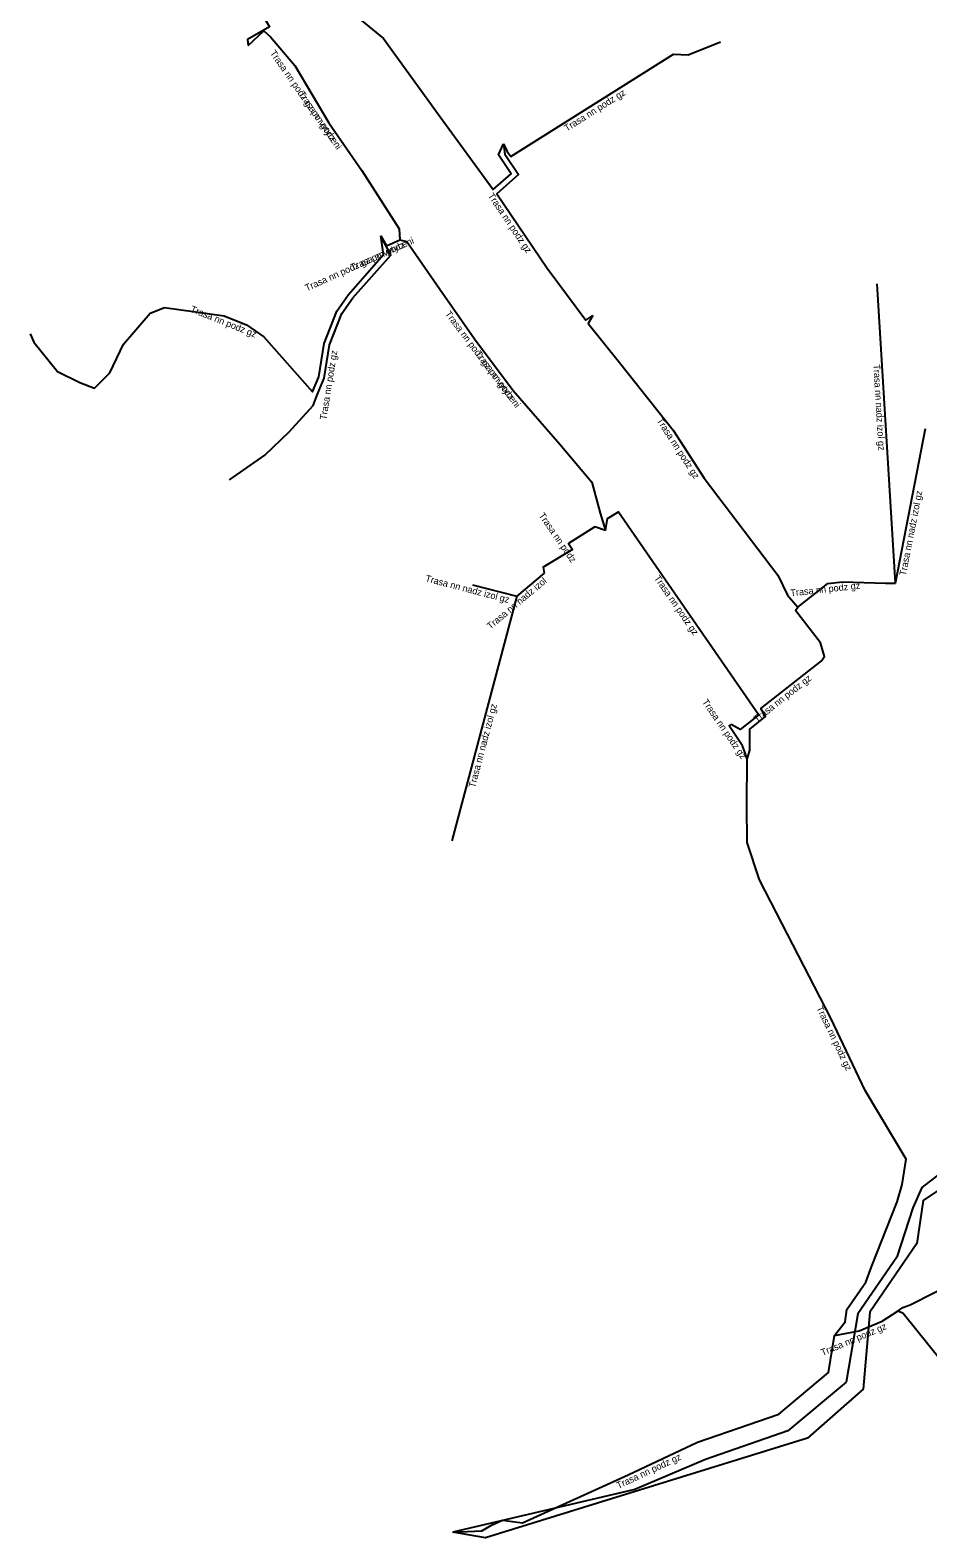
# Model space of a CAD drawing. Extents: x -484846 to -484244, y -1128177 to -1127608.
# Drawn here: x -484614.8 to -484548.8, y -1127966.4 to -1127855.5 of the extents above; entities that cross this region are included whole.
import ezdxf

# ---------------------------------------------------------------- set-up
doc = ezdxf.new("R2010")
doc.units = 0
for name, color, linetype in [('Popiskový text - Ostatní atributy Trasy', 7, 'Continuous'), ('Spojnice NN', 7, 'Continuous'), ('Spojnice VN', 7, 'Continuous')]:
    doc.layers.add(name, color=color, linetype=linetype)

msp = doc.modelspace()

# ---------------------------------------------------------------- linework, layer by layer
at = {"layer": 'Spojnice NN'}
for points in [[(-484612.77, -1127833.18), (-484612.69, -1127833.47), (-484612.45, -1127833.6), (-484612.24, -1127833.6), (-484611.12, -1127832.77), (-484610.26, -1127834.23), (-484608.68, -1127836.16), (-484602.59, -1127846.12), (-484597.23, -1127855.21), (-484598.85, -1127856.15), (-484598.8, -1127856.59)], [(-484599.31, -1127836.35), (-484600.73, -1127837.04), (-484599, -1127840.21), (-484594.48, -1127848.44), (-484591.27, -1127854.08), (-484588.85, -1127856.08), (-484584.69, -1127861.83), (-484580.78, -1127867.2), (-484579.45, -1127866.03), (-484580.4, -1127864.64), (-484580.01, -1127863.82)], [(-484598.8, -1127856.59), (-484597.66, -1127855.5), (-484597.15, -1127855.96), (-484595.37, -1127858.07), (-484592.87, -1127862.29), (-484590.45, -1127865.78), (-484587.69, -1127870.09), (-484587.64, -1127870.9)], [(-484598.8, -1127856.59), (-484597.66, -1127855.5), (-484597.15, -1127855.96), (-484595.37, -1127858.07), (-484592.87, -1127862.29), (-484590.45, -1127865.78), (-484587.69, -1127870.09), (-484587.64, -1127870.9)], [(-484580.01, -1127863.82), (-484579.74, -1127864.38), (-484579.47, -1127864.77), (-484567.52, -1127857.23), (-484566.44, -1127857.28), (-484564.05, -1127856.33)], [(-484580.01, -1127863.82), (-484579.93, -1127864.6), (-484578.93, -1127866.09), (-484580.52, -1127867.5), (-484576.82, -1127872.97), (-484573.97, -1127876.8), (-484573.45, -1127876.47)], [(-484614.84, -1127877.82), (-484614.56, -1127878.43), (-484612.82, -1127880.59), (-484611.19, -1127881.39), (-484610.1, -1127881.81), (-484608.98, -1127880.67), (-484607.97, -1127878.58), (-484606.01, -1127876.28), (-484604.95, -1127875.87), (-484600.57, -1127876.49), (-484598.92, -1127877.15), (-484597.66, -1127878.04), (-484594.07, -1127882.09), (-484593.6, -1127880.97), (-484593.21, -1127878.52), (-484592.27, -1127876.14), (-484591.43, -1127874.91), (-484588.84, -1127871.97), (-484589.05, -1127870.59)], [(-484600.19, -1127888.55), (-484597.57, -1127886.74), (-484595.8, -1127885.01), (-484594.02, -1127883.08), (-484593.7, -1127882.25), (-484593.22, -1127881.07), (-484592.83, -1127878.62), (-484591.91, -1127876.32), (-484591.11, -1127875.15), (-484588.32, -1127872.01), (-484589.05, -1127870.59)], [(-484589.05, -1127870.59), (-484588.62, -1127871.34), (-484587.64, -1127870.9)], [(-484589.05, -1127870.59), (-484588.62, -1127871.34), (-484587.64, -1127870.9)], [(-484587.64, -1127870.9), (-484587.13, -1127871.02), (-484584.71, -1127874.52), (-484582.15, -1127878.19), (-484579.3, -1127881.98), (-484575.88, -1127885.94), (-484573.53, -1127888.72), (-484572.92, -1127891.01), (-484572.52, -1127892.29)], [(-484587.64, -1127870.9), (-484587.13, -1127871.02), (-484584.71, -1127874.52), (-484582.15, -1127878.19), (-484579.3, -1127881.98), (-484575.88, -1127885.94), (-484573.53, -1127888.72), (-484572.92, -1127891.01), (-484572.52, -1127892.29)], [(-484551.19, -1127896.17), (-484552.53, -1127874.14)], [(-484573.45, -1127876.47), (-484573.79, -1127877.05), (-484571.48, -1127879.91), (-484567.54, -1127884.91), (-484565.26, -1127888.44), (-484559.85, -1127895.56), (-484559.13, -1127897.05), (-484558.38, -1127897.92)], [(-484551.19, -1127896.17), (-484548.97, -1127884.77)], [(-484572.52, -1127892.29), (-484572.38, -1127891.39), (-484571.56, -1127890.9), (-484561.25, -1127905.85), (-484562.62, -1127906.92), (-484563.27, -1127906.55)], [(-484572.52, -1127892.29), (-484573.3, -1127892.02), (-484575.24, -1127893.25), (-484574.94, -1127893.68), (-484577.1, -1127894.99), (-484577.03, -1127895.43)], [(-484577.03, -1127895.43), (-484579.04, -1127897.12)], [(-484582.3, -1127896.27), (-484579.04, -1127897.12)], [(-484558.38, -1127897.92), (-484556.17, -1127896.18), (-484555.08, -1127896.06), (-484551.91, -1127896.17), (-484551.19, -1127896.17)], [(-484579.04, -1127897.12), (-484583.82, -1127915.13)], [(-484562.1, -1127909.1), (-484561.89, -1127908.46), (-484561.9, -1127906.9), (-484560.74, -1127905.97), (-484561.09, -1127905.38), (-484556.65, -1127901.9), (-484556.41, -1127901.55), (-484556.69, -1127900.54), (-484558.55, -1127898.18), (-484558.38, -1127897.92)], [(-484562.1, -1127909.1), (-484562.3, -1127908.52), (-484562.43, -1127908.12), (-484563.43, -1127906.67), (-484563.27, -1127906.55)], [(-484555.68, -1127951.53), (-484554.88, -1127950.51), (-484554.76, -1127949.61), (-484553.36, -1127947.61), (-484552.94, -1127946.46), (-484551.06, -1127941.68), (-484550.7, -1127940.4), (-484550.4, -1127938.55), (-484553.41, -1127933.49), (-484555.95, -1127928.16), (-484559.51, -1127921.22), (-484561.2, -1127918), (-484562.09, -1127915.25), (-484562.11, -1127912.5), (-484562.1, -1127909.1)], [(-484550.99, -1127949.7), (-484550.64, -1127949.47), (-484550.11, -1127949.26), (-484539.5, -1127943.9)], [(-484555.68, -1127951.53), (-484553.85, -1127951.19), (-484552.17, -1127950.48), (-484550.99, -1127949.7)], [(-484550.99, -1127949.7), (-484550.63, -1127949.87), (-484547.79, -1127953.38), (-484546.05, -1127955.55), (-484543.69, -1127958.48), (-484541.77, -1127961.17), (-484541.98, -1127961.96), (-484541.62, -1127962.54), (-484541.55, -1127962.64), (-484541.35, -1127962.5)], [(-484583.75, -1127966), (-484581.62, -1127965.9), (-484580.9, -1127965.48), (-484580.09, -1127965.11), (-484578.63, -1127965.32), (-484570.85, -1127961.77), (-484565.74, -1127959.37), (-484559.77, -1127957.31), (-484556.12, -1127954.24), (-484555.68, -1127951.53)]]:
    msp.add_lwpolyline(points, dxfattribs=at)
at = {"layer": 'Spojnice VN'}
for points in [[(-484480.59, -1127857.59), (-484496.47, -1127860.34), (-484509.11, -1127863.16), (-484518.1, -1127868.51), (-484524.57, -1127875.5), (-484528.02, -1127881.9), (-484530.22, -1127886.66), (-484533.08, -1127893.91), (-484535.38, -1127902.51), (-484535.99, -1127907.75), (-484536.19, -1127917.12), (-484536.89, -1127924.1), (-484538.34, -1127928.78), (-484540.08, -1127932.28), (-484542.7, -1127935.58), (-484549.25, -1127940.63), (-484549.9, -1127942.12), (-484551.08, -1127945.75), (-484553.96, -1127949.92), (-484554.82, -1127954.96), (-484559.11, -1127958.53), (-484565.17, -1127960.65), (-484570.35, -1127962.86), (-484583.75, -1127966)], [(-484480.59, -1127857.59), (-484496.47, -1127860.34), (-484509.11, -1127863.16), (-484518.1, -1127868.51), (-484524.57, -1127875.5), (-484528.02, -1127881.9), (-484530.22, -1127886.66), (-484533.08, -1127893.91), (-484535.38, -1127902.51), (-484535.99, -1127907.75), (-484536.19, -1127917.12), (-484536.89, -1127924.1), (-484538.34, -1127928.78), (-484540.08, -1127932.28), (-484542.7, -1127935.58), (-484549.25, -1127940.63), (-484549.9, -1127942.12), (-484551.08, -1127945.75), (-484553.96, -1127949.92), (-484554.82, -1127954.96), (-484559.11, -1127958.53), (-484565.17, -1127960.65), (-484570.35, -1127962.86), (-484583.75, -1127966)], [(-484480.12, -1127859.03), (-484499.66, -1127862.34), (-484508.01, -1127864.39), (-484517.63, -1127869.9), (-484524.09, -1127876.36), (-484532.76, -1127895.75), (-484534.49, -1127910.87), (-484534.96, -1127919.7), (-484535.12, -1127922.85), (-484538.74, -1127932.46), (-484542.84, -1127937.35), (-484549.14, -1127941.6), (-484549.62, -1127944.75), (-484553.08, -1127949.8), (-484553.56, -1127955.47), (-484557.65, -1127959.09), (-484581.34, -1127966.42), (-484583.75, -1127966)]]:
    msp.add_lwpolyline(points, dxfattribs=at)

# ---------------------------------------------------------------- texts
at = {"layer": 'Popiskový text - Ostatní atributy Trasy'}
for s, rotation, p in [('Trasa nn podz gz po vytyceni', 304.7378, (-484597.23, -1127857.15)), ('Trasa nn podz', 304.7378, (-484595.13, -1127860.17)), ('Trasa nn podz gz', 32.222, (-484575.36, -1127862.94)), ('Trasa nn podz gz', 304.0607, (-484581.2, -1127867.65)), ('Trasa nn podz gz po vytyceni', 24.1791, (-484594.49, -1127874.69)), ('Trasa nn podz', 24.1791, (-484591.13, -1127873.18)), ('Trasa nn podz gz', 338.1986, (-484603.1, -1127876.18)), ('Trasa nn podz gz po vytyceni', 306.9424, (-484584.35, -1127876.35)), ('Trasa nn podz', 306.9424, (-484582.14, -1127879.29)), ('Trasa nn podz gz', 80.959, (-484593.05, -1127884.17)), ('Trasa nn nadz izol gz', 273.4682, (-484552.82, -1127880.07)), ('Trasa nn podz gz', 302.8581, (-484568.78, -1127884.19)), ('Trasa nn nadz izol gz', 78.9719, (-484550.42, -1127895.64)), ('Trasa nn podz', 304.6008, (-484577.46, -1127891.18)), ('Trasa nn nadz izol gz', 345.3675, (-484585.81, -1127896.02)), ('Trasa nn podz gz', 304.5966, (-484568.97, -1127895.79)), ('Trasa nn nadz izol', 40.0513, (-484580.98, -1127899.59)), ('Trasa nn podz gz', 6.2825, (-484558.89, -1127897.13)), ('Trasa nn podz gz', 38.0989, (-484561.38, -1127906.43)), ('Trasa nn nadz izol gz', 75.1572, (-484582.12, -1127911.25)), ('Trasa nn podz gz', 304.5821, (-484565.44, -1127904.9)), ('Trasa nn podz gz', 295.48, (-484557.02, -1127927.42)), ('Trasa nn podz gz', 22.9098, (-484556.55, -1127953.04)), ('Trasa nn podz gz', 25.1817, (-484571.57, -1127962.82))]:
    msp.add_text(s, height=0.5, rotation=rotation, dxfattribs=at).set_placement(p)

doc.saveas('drawing.dxf')
